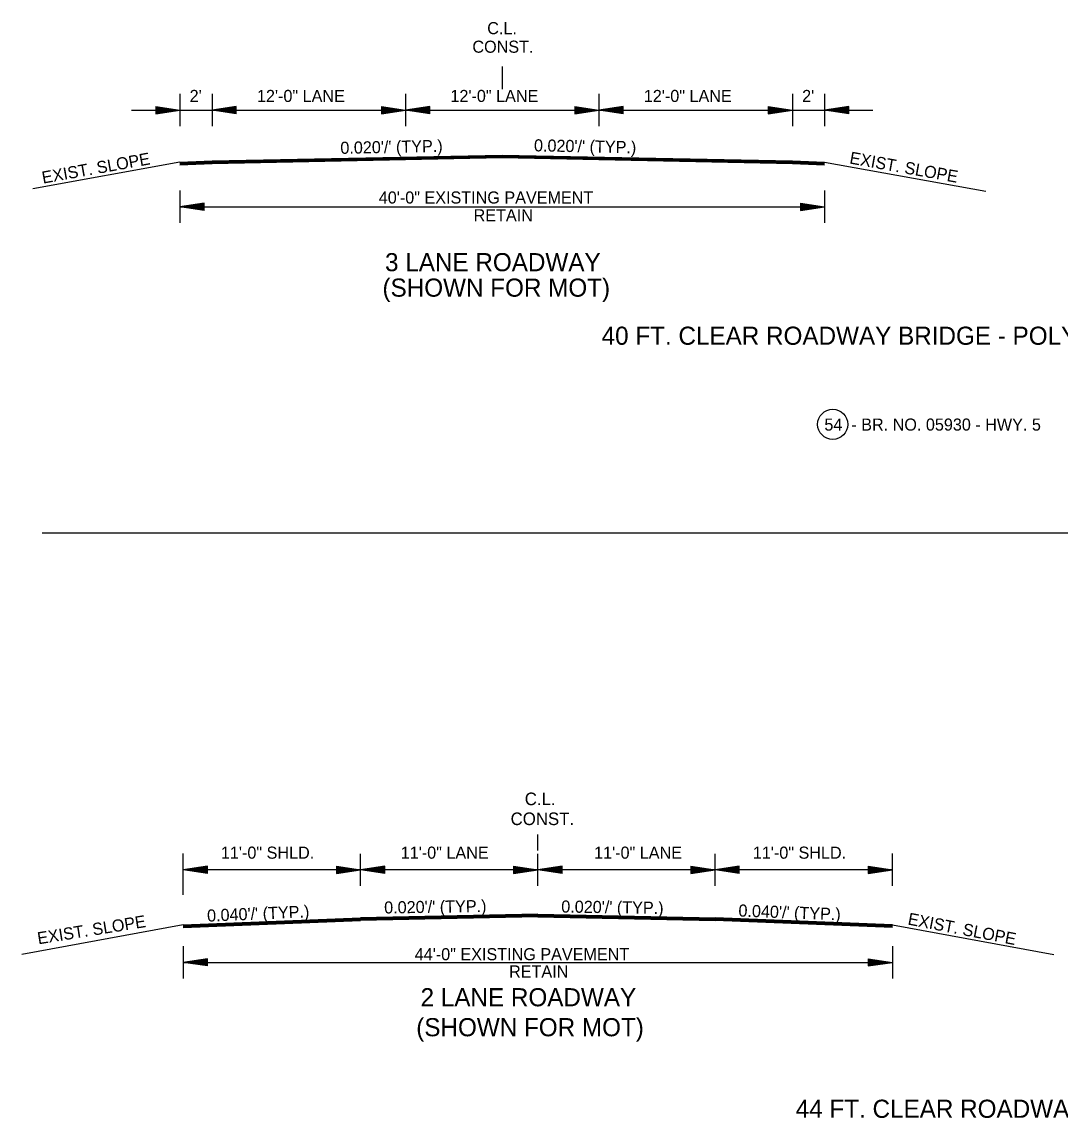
# Model space of a CAD drawing. Extents: x 550980 to 1930787, y -1972975 to 596640.
# Drawn here: x 550980 to 551625, y -1970315 to -1969634 of the extents above; entities that cross this region are included whole.
import ezdxf

# ---------------------------------------------------------------- set-up
doc = ezdxf.new("R2010")
doc.units = 0
doc.layers.add('R_Border', color=7, linetype='Continuous')
doc.layers.add('R_Draft', color=7, linetype='Continuous')

# ---------------------------------------------------------------- blocks, each defined once
blk = doc.blocks.new('BPPOLY')
at = {"layer": 'R_Border'}
blk.add_circle((0, 0), 9.34, dxfattribs=at)
blk = doc.blocks.new('ARROW')
at = {"layer": 'R_Draft'}
for p, q in [((-2, 0.3), (0, 0)), ((-2, 0.3), (-2, -0.3)), ((-2, 0.25), (-0.334, 0)), ((-2, 0.199), (-0.678, 0)), ((-2, 0.149), (-1.011, 0)), ((-2, 0.097), (-1.35, 0)), ((-2, 0.047), (-1.684, 0)), ((-2, -0.3), (0, 0)), ((-2, -0.098), (-1.35, 0)), ((-2, -0.199), (-0.678, 0)), ((-2, -0.25), (-0.334, 0)), ((-2, -0.149), (-1.011, 0)), ((-2, -0.047), (-1.684, 0))]:
    blk.add_line(p, q, dxfattribs=at)

msp = doc.modelspace()

# ---------------------------------------------------------------- linework, layer by layer
at = {"layer": 'R_Border'}
for p, q in [((551278.45, -1969662.14), (551278.45, -1969676.14)), ((551078.45, -1969679.14), (551078.45, -1969699.14)), ((551098.45, -1969679.14), (551098.45, -1969699.14)), ((551218.45, -1969679.14), (551218.45, -1969699.14)), ((551338.45, -1969679.14), (551338.45, -1969699.14)), ((551458.45, -1969679.14), (551458.45, -1969699.14)), ((551478.45, -1969679.14), (551478.45, -1969699.14)), ((551048.45, -1969689.14), (551508.45, -1969689.14)), ((551078.45, -1969721.54), (550987.18, -1969737.97)), ((551478.45, -1969721.54), (551578.45, -1969739.54)), ((551078.45, -1969739.14), (551078.45, -1969759.14)), ((551478.45, -1969739.14), (551478.45, -1969759.14)), ((551078.45, -1969749.14), (551478.45, -1969749.14)), ((550992.91, -1969951.43), (552054.18, -1969951.43))]:
    msp.add_line(p, q, dxfattribs=at)
for points in [[(551078.45, -1969721.54), (551098.45, -1969720.74), (551278.45, -1969717.14), (551458.45, -1969720.74), (551478.45, -1969721.54)], [(551078.45, -1969721.84), (551098.45, -1969721.04), (551278.45, -1969717.44), (551458.45, -1969721.04), (551478.45, -1969721.84)], [(551078.45, -1969722.14), (551098.45, -1969721.34), (551278.45, -1969717.74), (551458.45, -1969721.34), (551478.45, -1969722.14)], [(551078.45, -1969722.44), (551098.45, -1969721.64), (551278.45, -1969718.04), (551458.45, -1969721.64), (551478.45, -1969722.44)], [(551078.45, -1969722.74), (551098.45, -1969721.94), (551278.45, -1969718.34), (551458.45, -1969721.94), (551478.45, -1969722.74)], [(551078.45, -1969723.04), (551098.45, -1969722.24), (551278.45, -1969718.64), (551458.45, -1969722.24), (551478.45, -1969723.04)]]:
    msp.add_lwpolyline(points, dxfattribs=at)
at = {"layer": 'R_Draft'}
for p, q in [((551300.51, -1970148.46), (551300.51, -1970138.59)), ((551080.51, -1970175.95), (551080.51, -1970150.48)), ((551080.51, -1970170.48), (551080.51, -1970150.59)), ((551190.51, -1970170.48), (551190.51, -1970150.59)), ((551300.51, -1970170.48), (551300.51, -1970150.59)), ((551410.51, -1970170.48), (551410.51, -1970150.59)), ((551520.51, -1970170.48), (551520.51, -1970150.48)), ((551095.51, -1970158.23), (551080.51, -1970160.48)), ((551190.51, -1970160.48), (551080.51, -1970160.48)), ((551095.51, -1970162.73), (551080.51, -1970160.48)), ((551095.51, -1970158.6), (551083.01, -1970160.48)), ((551095.51, -1970162.35), (551083.01, -1970160.48)), ((551095.51, -1970158.99), (551085.59, -1970160.48)), ((551095.51, -1970161.97), (551085.59, -1970160.48)), ((551095.51, -1970159.36), (551088.09, -1970160.48)), ((551095.51, -1970161.6), (551088.09, -1970160.48)), ((551095.51, -1970159.74), (551090.63, -1970160.48)), ((551095.51, -1970161.21), (551090.63, -1970160.48)), ((551095.51, -1970160.13), (551093.14, -1970160.48)), ((551095.51, -1970160.83), (551093.14, -1970160.48)), ((551095.51, -1970162.73), (551095.51, -1970158.23)), ((551175.51, -1970158.23), (551190.51, -1970160.48)), ((551175.51, -1970158.23), (551175.51, -1970162.73)), ((551175.51, -1970158.6), (551188, -1970160.48)), ((551175.51, -1970158.99), (551185.42, -1970160.48)), ((551175.51, -1970159.36), (551182.92, -1970160.48)), ((551175.51, -1970159.75), (551180.38, -1970160.48)), ((551175.51, -1970160.13), (551177.88, -1970160.48)), ((551175.51, -1970162.73), (551190.51, -1970160.48)), ((551175.51, -1970161.21), (551180.38, -1970160.48)), ((551175.51, -1970161.97), (551185.42, -1970160.48)), ((551175.51, -1970162.35), (551188, -1970160.48)), ((551175.51, -1970161.6), (551182.92, -1970160.48)), ((551175.51, -1970160.83), (551177.88, -1970160.48)), ((551205.51, -1970158.23), (551190.51, -1970160.48)), ((551205.51, -1970162.73), (551190.51, -1970160.48)), ((551300.51, -1970160.48), (551190.51, -1970160.48)), ((551205.51, -1970158.6), (551193.01, -1970160.48)), ((551205.51, -1970162.35), (551193.01, -1970160.48)), ((551205.51, -1970158.99), (551195.59, -1970160.48)), ((551205.51, -1970161.97), (551195.59, -1970160.48)), ((551205.51, -1970159.36), (551198.09, -1970160.48)), ((551205.51, -1970161.6), (551198.09, -1970160.48)), ((551205.51, -1970159.74), (551200.63, -1970160.48)), ((551205.51, -1970161.21), (551200.63, -1970160.48)), ((551205.51, -1970160.13), (551203.14, -1970160.48)), ((551205.51, -1970160.83), (551203.14, -1970160.48)), ((551205.51, -1970162.73), (551205.51, -1970158.23)), ((551285.51, -1970158.23), (551300.51, -1970160.48)), ((551285.51, -1970158.23), (551285.51, -1970162.73)), ((551285.51, -1970158.6), (551298, -1970160.48)), ((551285.51, -1970158.99), (551295.42, -1970160.48)), ((551285.51, -1970159.36), (551292.92, -1970160.48)), ((551285.51, -1970159.75), (551290.38, -1970160.48)), ((551285.51, -1970160.13), (551287.88, -1970160.48)), ((551285.51, -1970162.73), (551300.51, -1970160.48)), ((551285.51, -1970161.21), (551290.38, -1970160.48)), ((551285.51, -1970161.97), (551295.42, -1970160.48)), ((551285.51, -1970162.35), (551298, -1970160.48)), ((551285.51, -1970161.6), (551292.92, -1970160.48)), ((551285.51, -1970160.83), (551287.88, -1970160.48)), ((551315.51, -1970158.23), (551300.51, -1970160.48)), ((551410.51, -1970160.48), (551300.51, -1970160.48)), ((551315.51, -1970162.73), (551300.51, -1970160.48)), ((551315.51, -1970158.6), (551303.01, -1970160.48)), ((551315.51, -1970162.35), (551303.01, -1970160.48)), ((551315.51, -1970158.99), (551305.59, -1970160.48)), ((551315.51, -1970161.97), (551305.59, -1970160.48)), ((551315.51, -1970159.36), (551308.09, -1970160.48)), ((551315.51, -1970161.6), (551308.09, -1970160.48)), ((551315.51, -1970159.74), (551310.63, -1970160.48)), ((551315.51, -1970161.21), (551310.63, -1970160.48)), ((551315.51, -1970160.13), (551313.14, -1970160.48)), ((551315.51, -1970160.83), (551313.14, -1970160.48)), ((551315.51, -1970162.73), (551315.51, -1970158.23)), ((551395.51, -1970158.23), (551410.51, -1970160.48)), ((551395.51, -1970158.23), (551395.51, -1970162.73)), ((551395.51, -1970158.6), (551408, -1970160.48)), ((551395.51, -1970158.99), (551405.42, -1970160.48)), ((551395.51, -1970159.36), (551402.92, -1970160.48)), ((551395.51, -1970159.75), (551400.38, -1970160.48)), ((551395.51, -1970160.13), (551397.88, -1970160.48)), ((551395.51, -1970162.73), (551410.51, -1970160.48)), ((551395.51, -1970161.21), (551400.38, -1970160.48)), ((551395.51, -1970161.97), (551405.42, -1970160.48)), ((551395.51, -1970162.35), (551408, -1970160.48)), ((551395.51, -1970161.6), (551402.92, -1970160.48)), ((551395.51, -1970160.83), (551397.88, -1970160.48)), ((551520.5, -1970160.48), (551410.5, -1970160.48)), ((551425.51, -1970158.23), (551410.51, -1970160.48)), ((551425.51, -1970162.73), (551410.51, -1970160.48)), ((551425.51, -1970158.6), (551413.01, -1970160.48)), ((551425.51, -1970162.35), (551413.01, -1970160.48)), ((551425.51, -1970158.99), (551415.59, -1970160.48)), ((551425.51, -1970161.97), (551415.59, -1970160.48)), ((551425.51, -1970159.36), (551418.09, -1970160.48)), ((551425.51, -1970161.6), (551418.09, -1970160.48)), ((551425.51, -1970159.74), (551420.63, -1970160.48)), ((551425.51, -1970161.21), (551420.63, -1970160.48)), ((551425.51, -1970160.13), (551423.14, -1970160.48)), ((551425.51, -1970160.83), (551423.14, -1970160.48)), ((551425.51, -1970162.73), (551425.51, -1970158.23)), ((551505.5, -1970158.23), (551520.5, -1970160.48)), ((551505.5, -1970158.23), (551505.5, -1970162.73)), ((551505.5, -1970158.6), (551518, -1970160.48)), ((551505.5, -1970158.99), (551515.42, -1970160.48)), ((551505.5, -1970159.36), (551512.92, -1970160.48)), ((551505.5, -1970159.75), (551510.38, -1970160.48)), ((551505.5, -1970160.13), (551507.87, -1970160.48)), ((551505.5, -1970162.73), (551520.5, -1970160.48)), ((551505.5, -1970161.21), (551510.38, -1970160.48)), ((551505.5, -1970161.97), (551515.42, -1970160.48)), ((551505.5, -1970162.35), (551518, -1970160.48)), ((551505.5, -1970161.6), (551512.92, -1970160.48)), ((551505.5, -1970160.83), (551507.87, -1970160.48)), ((551080.51, -1970194.69), (551190.51, -1970190.29)), ((551080.51, -1970194.99), (551190.51, -1970190.59)), ((551300.51, -1970188.09), (551190.51, -1970190.29)), ((551300.51, -1970188.39), (551190.51, -1970190.59)), ((551300.52, -1970188.69), (551190.51, -1970190.89)), ((551300.52, -1970188.99), (551190.51, -1970191.19)), ((551300.53, -1970189.29), (551190.51, -1970191.49)), ((551300.54, -1970189.58), (551190.51, -1970191.79)), ((551300.54, -1970189.78), (551190.51, -1970191.99)), ((551300.47, -1970189.78), (551410.51, -1970191.99)), ((551300.48, -1970189.29), (551410.51, -1970191.49)), ((551300.48, -1970189.58), (551410.51, -1970191.79)), ((551300.49, -1970188.69), (551410.51, -1970190.89)), ((551300.49, -1970188.99), (551410.51, -1970191.19)), ((551300.5, -1970188.39), (551410.51, -1970190.59)), ((551300.51, -1970188.09), (551410.51, -1970190.29)), ((551520.51, -1970194.69), (551410.51, -1970190.29)), ((551520.51, -1970194.99), (551410.51, -1970190.59)), ((551080.51, -1970194.69), (550980.44, -1970213.06)), ((551080.51, -1970195.29), (551190.51, -1970190.89)), ((551080.51, -1970195.59), (551190.51, -1970191.19)), ((551080.51, -1970195.89), (551190.51, -1970191.49)), ((551080.51, -1970196.19), (551190.51, -1970191.79)), ((551080.51, -1970196.39), (551190.51, -1970191.99)), ((551520.51, -1970195.29), (551410.51, -1970190.89)), ((551520.51, -1970195.59), (551410.51, -1970191.19)), ((551520.51, -1970195.89), (551410.51, -1970191.49)), ((551520.51, -1970196.19), (551410.51, -1970191.79)), ((551520.51, -1970196.39), (551410.51, -1970191.99)), ((551520.51, -1970194.69), (551620.57, -1970213.06)), ((551080.51, -1970207.94), (551080.51, -1970227.94)), ((551520.51, -1970207.94), (551520.51, -1970227.94)), ((551095.51, -1970215.69), (551080.51, -1970217.94)), ((551080.51, -1970217.94), (551520.51, -1970217.94)), ((551095.51, -1970220.19), (551080.51, -1970217.94)), ((551095.51, -1970216.07), (551083.01, -1970217.94)), ((551095.51, -1970219.82), (551083.01, -1970217.94)), ((551095.51, -1970216.45), (551085.59, -1970217.94)), ((551095.51, -1970219.44), (551085.59, -1970217.94)), ((551095.51, -1970216.83), (551088.09, -1970217.94)), ((551095.51, -1970219.06), (551088.09, -1970217.94)), ((551095.51, -1970217.21), (551090.63, -1970217.94)), ((551095.51, -1970218.67), (551090.63, -1970217.94)), ((551095.51, -1970217.59), (551093.14, -1970217.94)), ((551095.51, -1970218.3), (551093.14, -1970217.94)), ((551095.51, -1970220.19), (551095.51, -1970215.69)), ((551505.51, -1970215.69), (551520.51, -1970217.94)), ((551505.51, -1970215.69), (551505.51, -1970220.19)), ((551505.51, -1970216.07), (551518, -1970217.94)), ((551505.51, -1970216.45), (551515.42, -1970217.94)), ((551505.51, -1970216.83), (551512.92, -1970217.94)), ((551505.51, -1970217.22), (551510.38, -1970217.94)), ((551505.51, -1970217.59), (551507.88, -1970217.94)), ((551505.51, -1970220.19), (551520.51, -1970217.94)), ((551505.51, -1970218.68), (551510.38, -1970217.94)), ((551505.51, -1970219.44), (551515.42, -1970217.94)), ((551505.51, -1970219.82), (551518, -1970217.94)), ((551505.51, -1970219.06), (551512.92, -1970217.94)), ((551505.51, -1970218.3), (551507.88, -1970217.94))]:
    msp.add_line(p, q, dxfattribs=at)

# ---------------------------------------------------------------- block references
at = {"layer": 'R_Border', "xscale": 7.5, "yscale": 7.5}
for p in [(551078.45, -1969689.14), (551218.45, -1969689.14), (551338.45, -1969689.14), (551338.45, -1969689.14), (551458.45, -1969689.14), (551478.45, -1969749.14)]:
    msp.add_blockref('ARROW', p, dxfattribs=at)
at = {"layer": 'R_Border', "xscale": 7.5, "yscale": 7.5, "rotation": 180}
for p in [(551098.45, -1969689.14), (551218.45, -1969689.14), (551338.45, -1969689.14), (551478.45, -1969689.14), (551078.45, -1969749.14)]:
    msp.add_blockref('ARROW', p, dxfattribs=at)
at = {"layer": 'R_Border'}
msp.add_blockref('BPPOLY', (551483.45, -1969884.14), dxfattribs=at)

# ---------------------------------------------------------------- texts
for s, height, p in [('C.L.', 7.5, (551269.12, -1969642.08)), ('CONST.', 7.5, (551259.91, -1969653.58)), ("2'", 7.5, (551084.5, -1969684.14)), ('12\'-0" LANE', 7.5, (551126.27, -1969684.14)), ('12\'-0" LANE', 7.5, (551246.27, -1969684.14)), ('12\'-0" LANE', 7.5, (551366.27, -1969684.14)), ("2'", 7.5, (551464.5, -1969684.14)), ('40\'-0" EXISTING PAVEMENT', 7.5, (551201.83, -1969747.14)), ('RETAIN', 7.5, (551260.65, -1969758.14)), ('3 LANE ROADWAY', 11.25, (551205.73, -1969789.14)), ('(SHOWN FOR MOT)', 11.25, (551204.13, -1969804.93)), ('40 FT. CLEAR ROADWAY BRIDGE - POLYMER OVERLAY', 11.25, (551340.09, -1969834.77)), ('(SHOWN FOR MOT)', 11.25, (551225.07, -1970263.79))]:
    msp.add_text(s, height=height, dxfattribs=at).set_placement(p)
for s, rotation, p in [("0.020'/' (TYP.)", 1.1458, (551178.07, -1969716.35)), ("0.020'/' (TYP.)", 358.8542, (551298.07, -1969714.73)), ('EXIST. SLOPE', 10.204, (550993.52, -1969734.83)), ('EXIST. SLOPE', 349.796, (551493.52, -1969722.25))]:
    msp.add_text(s, height=7.5, rotation=rotation, dxfattribs=at).set_placement(p)
at = {"layer": 'R_Draft'}
for s, height, p in [('54  - BR. NO. 05930 - HWY. 5', 7.5, (551478.29, -1969888.02)), ('C.L.', 7.8, (551292.4, -1970120.4)), ('CONST.', 7.8, (551283.62, -1970132.76)), ('11\'-0" SHLD.', 7.5, (551103.91, -1970153.62)), ('11\'-0" LANE', 7.5, (551215.45, -1970153.62)), ('11\'-0" LANE', 7.5, (551335.41, -1970153.62)), ('11\'-0" SHLD.', 7.5, (551433.91, -1970153.62)), ('44\'-0" EXISTING PAVEMENT', 7.5, (551224.14, -1970216.62)), ('RETAIN', 7.5, (551282.66, -1970227.34)), ('2 LANE ROADWAY', 11.25, (551227.78, -1970245.19)), ('44 FT. CLEAR ROADWAY BRIDGE - POLYMER OVERLAY', 11.25, (551460.51, -1970314.38))]:
    msp.add_text(s, height=height, dxfattribs=at).set_placement(p)
for s, rotation, p in [("0.040'/' (TYP.)", 2.44797, (551095.47, -1970192.71)), ("0.020'/' (TYP.)", 0.87191, (551205.23, -1970187.65)), ("0.020'/' (TYP.)", 359.16404, (551315.01, -1970186.99)), ("0.040'/' (TYP.)", 357.81683, (551424.86, -1970189.45)), ('EXIST. SLOPE', 9.15344, (550990.64, -1970206.79)), ('EXIST. SLOPE', 349.11714, (551529.63, -1970194.41))]:
    msp.add_text(s, height=7.5, rotation=rotation, dxfattribs=at).set_placement(p)

doc.saveas('drawing.dxf')
